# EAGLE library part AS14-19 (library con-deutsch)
DEUTSCH Connector
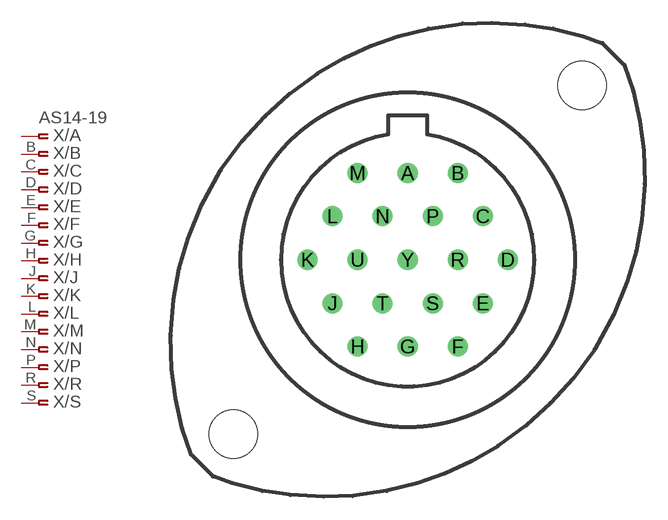
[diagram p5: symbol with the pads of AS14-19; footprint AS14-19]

Designator prefix X; gates /A=PINF_VAL /B=ASPINF /C=ASPINF /D=ASPINF /E=ASPINF /F=ASPINF /G=ASPINF /H=ASPINF /J=ASPINF /K=ASPINF /L=ASPINF /M=ASPINF /N=ASPINF /P=ASPINF /R=ASPINF /S=ASPINF /T=ASPINF /U=ASPINF /Y=ASPINF

## AS14-19 (OC_FARNELL: unknown; OC_NEWARK: unknown)  [AS14-19]
A  /A:1  pas
B  /B:1  pas
C  /C:1  pas
D  /D:1  pas
E  /E:1  pas
F  /F:1  pas
G  /G:1  pas
H  /H:1  pas
J  /J:1  pas
K  /K:1  pas
L  /L:1  pas
M  /M:1  pas
N  /N:1  pas
P  /P:1  pas
R  /R:1  pas
S  /S:1  pas
T  /T:1  pas
U  /U:1  pas
Y  /Y:1  pas

## Footprint AS14-19 (pad centres in mm)
DEUTSCH Connector
drill 0.813 round: A 0,5.715; B 3.302,5.715; C 4.953,2.87; D 6.604,0; E 4.953,-2.87; F 3.302,-5.715; G 0,-5.715; H -3.302,-5.715; J -4.953,-2.87; K -6.604,0; L -4.953,2.87; M -3.302,5.715; N -1.651,2.87; P 1.651,2.87; R 3.302,0; S 1.651,-2.87; T -1.651,-2.87; U -3.302,0; Y 0,0
hole 3.2 at 11.493,11.493
hole 3.2 at -11.493,-11.493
